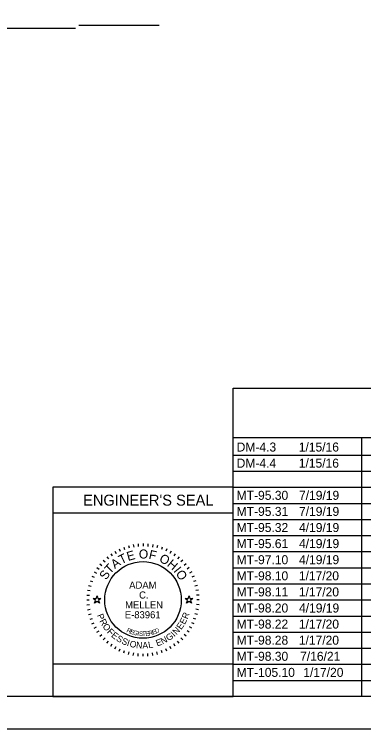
# Model space of a CAD drawing. Extents: x 0 to 34, y 0 to 22.
# Drawn here: x 6.75 to 12.18, y 0 to 11.1 of the extents above; entities that cross this region are included whole.
import ezdxf

# ---------------------------------------------------------------- set-up
doc = ezdxf.new("R2010")
doc.units = 0
for name, color, linetype in [('Default', 7, 'Continuous'), ('SH_Border', 7, 'Continuous'), ('SH_Cut_Line', 7, 'Continuous'), ('SH_Data', 7, 'Continuous'), ('SH_Text', 7, 'Continuous')]:
    doc.layers.add(name, color=color, linetype=linetype)

msp = doc.modelspace()

# ---------------------------------------------------------------- linework, layer by layer
at = {"layer": 'Default'}
for points in [[(7.974, 2.02), (8.021, 2.02), (8.035, 2.065), (8.049, 2.02), (8.096, 2.02), (8.058, 1.992), (8.073, 1.948), (8.035, 1.975), (7.997, 1.948), (8.012, 1.992)], [(9.404, 2.02), (9.451, 2.02), (9.465, 2.065), (9.479, 2.02), (9.526, 2.02), (9.488, 1.992), (9.503, 1.948), (9.465, 1.975), (9.427, 1.948), (9.442, 1.992)]]:
    msp.add_lwpolyline(points, close=True, dxfattribs=at)
at = {"layer": 'SH_Border'}
msp.add_lwpolyline([(1.5, 21.5), (33.5, 21.5), (33.5, 0.5), (1.5, 0.5)], close=True, dxfattribs=at)
at = {"layer": 'SH_Cut_Line'}
msp.add_lwpolyline([(0, 0), (34, 0), (34, 22), (0, 22)], close=True, dxfattribs=at)
at = {"layer": 'SH_Data'}
for p, q in [((7.7, 10.877), (3.347, 10.877)), ((9, 10.922), (7.75, 10.922)), ((10.15, 5.292), (23.6, 5.292)), ((10.15, 0.5), (10.15, 5.292)), ((10.15, 4.521), (23.6, 4.521)), ((12.15, 0.5), (12.15, 4.521)), ((10.15, 4.25), (23.6, 4.25)), ((10.15, 4), (23.6, 4)), ((10.15, 3.75), (7.35, 3.75)), ((7.35, 3.75), (7.35, 0.5)), ((10.15, 3.75), (23.6, 3.75)), ((10.15, 0.5), (10.15, 3.75)), ((10.15, 0.5), (10.15, 3.75)), ((10.15, 3.5), (23.6, 3.5)), ((10.15, 3.35), (7.35, 3.35)), ((10.15, 3.25), (23.6, 3.25)), ((10.15, 3), (23.6, 3)), ((8.38, 2.793), (8.397, 2.757)), ((8.451, 2.822), (8.464, 2.785)), ((8.524, 2.845), (8.534, 2.807)), ((8.598, 2.862), (8.605, 2.822)), ((8.674, 2.872), (8.677, 2.832)), ((8.75, 2.875), (8.75, 2.835)), ((8.826, 2.872), (8.823, 2.832)), ((8.902, 2.862), (8.895, 2.822)), ((8.976, 2.845), (8.966, 2.807)), ((9.049, 2.822), (9.036, 2.785)), ((9.12, 2.793), (9.103, 2.757)), ((8.188, 2.67), (8.213, 2.64)), ((8.248, 2.717), (8.271, 2.684)), ((8.313, 2.758), (8.333, 2.723)), ((9.187, 2.758), (9.167, 2.723)), ((9.252, 2.717), (9.229, 2.684)), ((9.312, 2.67), (9.287, 2.64)), ((10.15, 2.75), (23.6, 2.75)), ((8.08, 2.562), (8.11, 2.537)), ((8.131, 2.619), (8.16, 2.59)), ((9.369, 2.619), (9.34, 2.59)), ((9.42, 2.562), (9.39, 2.537)), ((8.033, 2.502), (8.066, 2.479)), ((9.467, 2.502), (9.434, 2.479)), ((10.15, 2.5), (23.6, 2.5)), ((7.957, 2.37), (7.993, 2.353)), ((7.992, 2.438), (8.027, 2.418)), ((9.508, 2.438), (9.473, 2.418)), ((9.543, 2.37), (9.507, 2.353)), ((7.905, 2.226), (7.943, 2.216)), ((7.928, 2.299), (7.965, 2.286)), ((9.572, 2.299), (9.535, 2.286)), ((9.595, 2.226), (9.557, 2.216)), ((10.15, 2.25), (23.6, 2.25)), ((7.888, 2.152), (7.928, 2.145)), ((9.612, 2.152), (9.572, 2.145)), ((7.875, 2), (7.915, 2)), ((7.878, 2.076), (7.918, 2.073)), ((9.622, 2.076), (9.582, 2.073)), ((9.625, 2), (9.585, 2)), ((10.15, 2), (23.6, 2)), ((7.878, 1.924), (7.918, 1.927)), ((9.622, 1.924), (9.582, 1.927)), ((7.888, 1.848), (7.928, 1.855)), ((7.905, 1.774), (7.943, 1.784)), ((9.595, 1.774), (9.557, 1.784)), ((9.612, 1.848), (9.572, 1.855)), ((7.928, 1.701), (7.965, 1.714)), ((9.572, 1.701), (9.535, 1.714)), ((10.15, 1.75), (23.6, 1.75)), ((7.957, 1.63), (7.993, 1.647)), ((7.992, 1.563), (8.027, 1.583)), ((9.508, 1.563), (9.473, 1.583)), ((9.543, 1.63), (9.507, 1.647)), ((8.033, 1.498), (8.066, 1.521)), ((8.08, 1.438), (8.11, 1.463)), ((9.42, 1.438), (9.39, 1.463)), ((9.467, 1.498), (9.434, 1.521)), ((10.15, 1.5), (23.6, 1.5)), ((8.131, 1.381), (8.16, 1.41)), ((8.188, 1.33), (8.213, 1.36)), ((9.312, 1.33), (9.287, 1.36)), ((9.369, 1.381), (9.34, 1.41)), ((8.248, 1.283), (8.271, 1.316)), ((8.313, 1.242), (8.333, 1.277)), ((8.38, 1.207), (8.397, 1.243)), ((9.12, 1.207), (9.103, 1.243)), ((9.187, 1.242), (9.167, 1.277)), ((9.252, 1.283), (9.229, 1.316)), ((10.15, 1.25), (23.6, 1.25)), ((8.451, 1.178), (8.464, 1.215)), ((8.524, 1.155), (8.534, 1.193)), ((8.598, 1.138), (8.605, 1.178)), ((8.674, 1.128), (8.677, 1.168)), ((8.75, 1.125), (8.75, 1.165)), ((8.826, 1.128), (8.823, 1.168)), ((8.902, 1.138), (8.895, 1.178)), ((8.976, 1.155), (8.966, 1.193)), ((9.049, 1.178), (9.036, 1.215)), ((10.15, 1), (23.6, 1)), ((10.15, 0.75), (23.6, 0.75)), ((10.15, 0.5), (7.35, 0.5)), ((10.15, 0.5), (7.35, 0.5))]:
    msp.add_line(p, q, dxfattribs=at)
msp.add_lwpolyline([(10.15, 0.5), (10.15, 1), (7.35, 1), (7.35, 0.5)], close=True, dxfattribs=at)
msp.add_circle((8.75, 2), 0.595, dxfattribs=at)

# ---------------------------------------------------------------- texts
for s, height, p in [("ENGINEER'S SEAL", 0.17, (7.818, 3.465)), ('ADAM', 0.11, (8.535, 2.175)), ('C.', 0.11, (8.689, 2.022)), ('MELLEN', 0.11, (8.472, 1.868)), ('E-83961', 0.11, (8.467, 1.715))]:
    msp.add_text(s, height=height, dxfattribs=at).set_placement(p)
for s, height, rotation, p in [('O', 0.14, 359.7812, (8.685, 2.644)), ('F', 0.14, 347.4362, (8.831, 2.642)), ('T', 0.14, 25.7167, (8.412, 2.552)), ('E', 0.14, 15.7571, (8.518, 2.604)), ('O', 0.14, 332.2586, (8.99, 2.602)), ('T', 0.14, 46.4344, (8.238, 2.396)), ('A', 0.14, 36.4747, (8.313, 2.478)), ('H', 0.14, 319.9136, (9.113, 2.536)), ('S', 0.14, 57.1924, (8.178, 2.301)), ('I', 0.14, 308.367, (9.216, 2.448)), ('O', 0.14, 303.1491, (9.252, 2.409)), ('P', 0.1, 291.494, (8.032, 1.762)), ('R', 0.1, 69.2322, (9.442, 1.695)), ('R', 0.1, 298.7311, (8.069, 1.672)), ('E', 0.1, 61.9951, (9.398, 1.61)), ('O', 0.1, 306.4666, (8.115, 1.588)), ('F', 0.1, 314.7068, (8.184, 1.498)), ('R', 0.07, 334.487, (8.487, 1.505)), ('D', 0.07, 23.3052, (8.951, 1.477)), ('N', 0.1, 47.0224, (9.27, 1.451)), ('E', 0.1, 54.758, (9.343, 1.531)), ('E', 0.1, 321.4393, (8.248, 1.435)), ('S', 0.1, 328.6764, (8.324, 1.375)), ('E', 0.07, 341.04, (8.541, 1.48)), ('G', 0.07, 347.4752, (8.591, 1.462)), ('I', 0.07, 353.7858, (8.659, 1.447)), ('S', 0.07, 356.8926, (8.686, 1.443)), ('T', 0.07, 3.0061, (8.736, 1.439)), ('E', 0.07, 6.0117, (8.789, 1.441)), ('R', 0.07, 11.9184, (8.842, 1.447)), ('E', 0.07, 17.6836, (8.9, 1.46)), ('G', 0.1, 35.0469, (9.148, 1.357)), ('I', 0.1, 43.287, (9.237, 1.421)), ('S', 0.1, 335.9134, (8.406, 1.327)), ('I', 0.1, 343.1505, (8.491, 1.29)), ('O', 0.1, 346.8859, (8.534, 1.275)), ('N', 0.1, 355.1261, (8.639, 1.252)), ('A', 0.1, 2.8617, (8.742, 1.244)), ('L', 0.1, 10.0987, (8.839, 1.249)), ('E', 0.1, 20.0742, (8.971, 1.277)), ('N', 0.1, 27.3113, (9.054, 1.308))]:
    msp.add_text(s, height=height, rotation=rotation, dxfattribs=at).set_placement(p)
at = {"layer": 'SH_Text'}
for s, p in [('DM-4.3', (10.205, 4.305)), ('1/15/16', (11.17, 4.305)), ('DM-4.4', (10.205, 4.055)), ('1/15/16', (11.17, 4.055)), ('MT-95.30', (10.205, 3.555)), ('7/19/19', (11.174, 3.555)), ('MT-95.31', (10.205, 3.305)), ('7/19/19', (11.174, 3.305)), ('MT-95.32', (10.205, 3.055)), ('4/19/19', (11.174, 3.055)), ('MT-95.61', (10.205, 2.805)), ('4/19/19', (11.174, 2.805)), ('MT-97.10', (10.205, 2.555)), ('4/19/19', (11.174, 2.555)), ('MT-98.10', (10.205, 2.305)), ('1/17/20', (11.171, 2.305)), ('MT-98.11', (10.205, 2.055)), ('1/17/20', (11.171, 2.055)), ('MT-98.20', (10.205, 1.805)), ('4/19/19', (11.174, 1.805)), ('MT-98.22', (10.205, 1.555)), ('1/17/20', (11.171, 1.555)), ('MT-98.28', (10.205, 1.305)), ('1/17/20', (11.171, 1.305)), ('MT-98.30', (10.205, 1.055)), ('7/16/21', (11.191, 1.055)), ('MT-105.10', (10.205, 0.805)), ('1/17/20', (11.24, 0.805))]:
    msp.add_text(s, height=0.14, dxfattribs=at).set_placement(p)

doc.saveas('drawing.dxf')
